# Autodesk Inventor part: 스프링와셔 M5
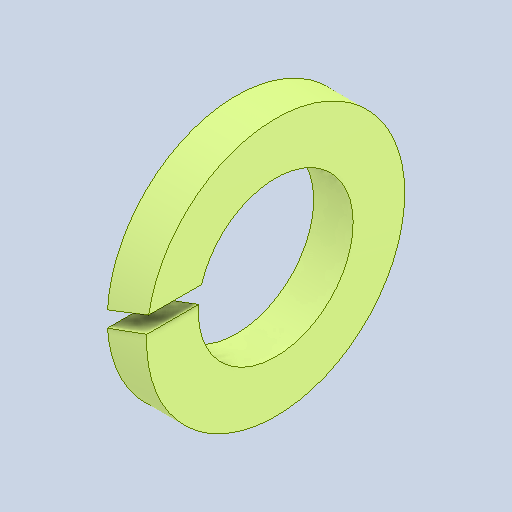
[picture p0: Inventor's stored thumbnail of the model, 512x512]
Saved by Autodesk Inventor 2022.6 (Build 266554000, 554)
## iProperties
Created: 2024-09
Part Number: 스프링와셔 M5
Material: 강철, 연강
Description: 스프링 잠금 와셔
Document SubType Name: Modeling
Designer: Class 001
Density: 7.85 g/cm^3
Appearance: 기본값
Author: jhkim
Sending System: Autodesk Inventor 2025
Preprocessor: ST-DEVELOPER v20
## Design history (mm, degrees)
feature "Solid1"
node "솔리드1"
